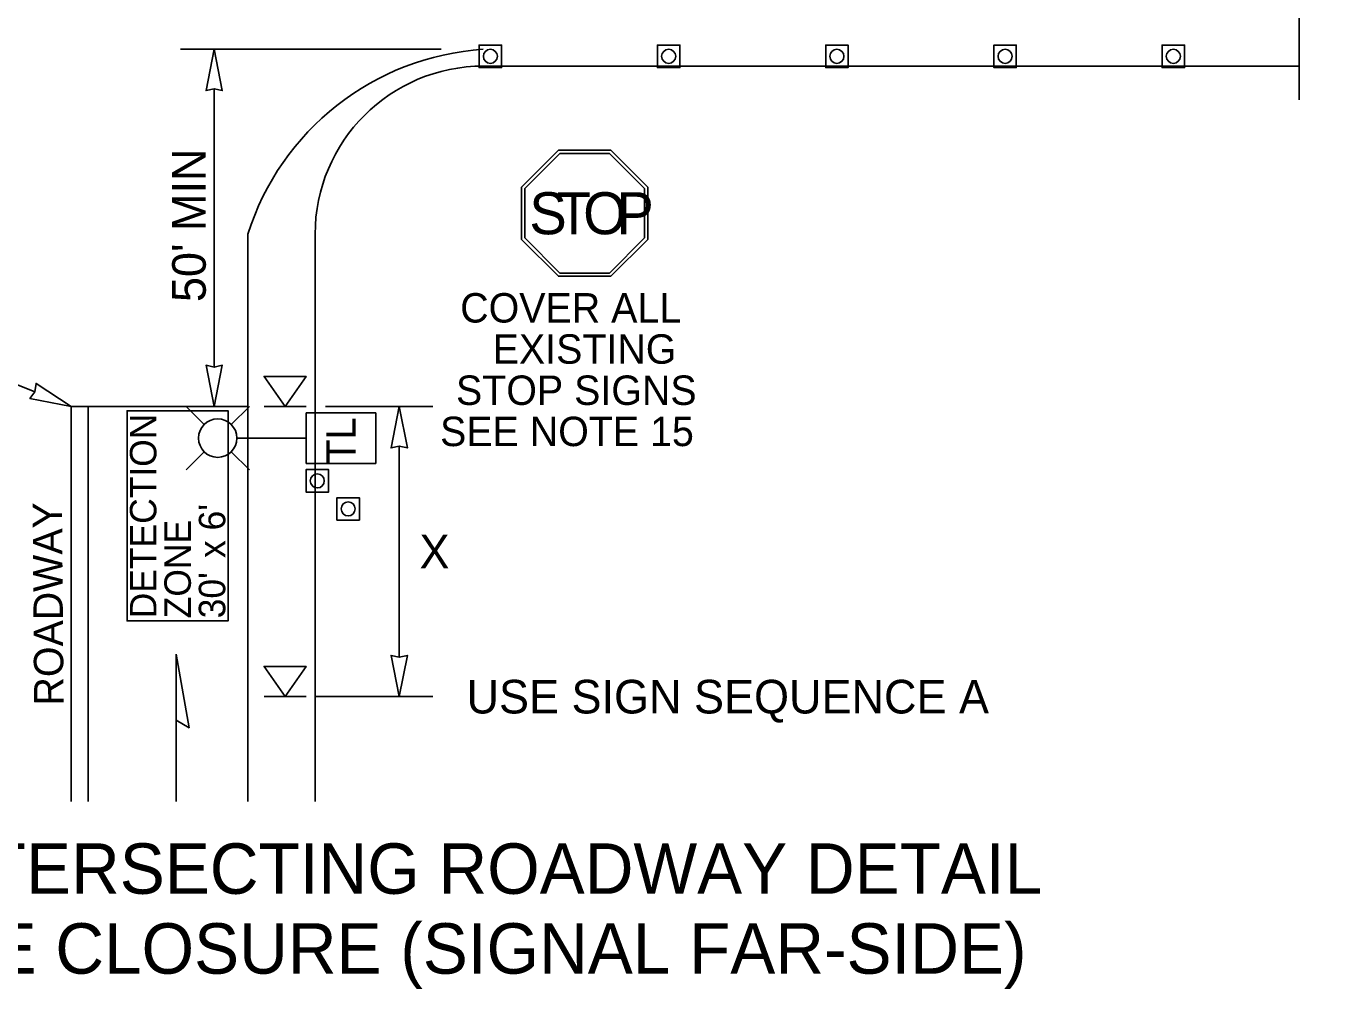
# Model space of a CAD drawing. Extents: x 99979.8 to 100075.7, y 99995 to 100010.7.
# Drawn here: x 100041.998 to 100045.105, y 100006.224 to 100008.515 of the extents above; entities that cross this region are included whole.
import ezdxf

# ---------------------------------------------------------------- set-up
doc = ezdxf.new("R2010")
doc.units = 0
for name, color, linetype in [('RD_ED_ShoulderPavedEdge', 7, 'Continuous'), ('RD_MK_LineDblYellowCenter', 7, 'Continuous'), ('RD_MK_LineEdgeWhite', 7, 'Continuous'), ('RD_MK_LineStop', 7, 'Continuous'), ('SH_DE_DetailBody1Text', 7, 'Continuous'), ('SH_DE_DetailHeading2Text', 7, 'Continuous'), ('TR_SN_ConstructionSigns', 7, 'Continuous'), ('TR_WZ_PortableLightStandard', 7, 'Continuous'), ('TR_WZ_PortableSignMountBlk-Org', 7, 'Continuous'), ('TR_WZ_PortableSignMountBlk-Wht', 7, 'Continuous'), ('TR_WZ_TrafficCone', 7, 'Continuous'), ('TR_WZ_WorkZoneDetails', 7, 'Continuous'), ('TR_WZ_WorkZoneTextCurrent', 7, 'Continuous')]:
    doc.layers.add(name, color=color, linetype=linetype)

msp = doc.modelspace()

# ---------------------------------------------------------------- linework, layer by layer
at = {"layer": 'RD_ED_ShoulderPavedEdge'}
msp.add_line((100043.085, 100008.4195), (100045.025, 100008.4195), dxfattribs=at)
msp.add_lwpolyline([(100042.685, 100006.6704), (100042.685, 100008.0195)], dxfattribs=at)
msp.add_arc((100043.085, 100008.0195), 0.4, 90, 180, dxfattribs=at)
at = {"layer": 'RD_MK_LineDblYellowCenter'}
for p, q in [((100042.105, 100006.6704), (100042.105, 100007.6095)), ((100042.145, 100006.6704), (100042.145, 100007.6095))]:
    msp.add_line(p, q, dxfattribs=at)
at = {"layer": 'RD_MK_LineEdgeWhite'}
msp.add_line((100042.525, 100008.0195), (100042.525, 100006.6704), dxfattribs=at)
msp.add_arc((100043.1265, 100007.8303), 0.6306, 93.7766, 162.5378, dxfattribs=at)
at = {"layer": 'RD_MK_LineStop'}
msp.add_line((100042.525, 100007.6095), (100042.105, 100007.6095), dxfattribs=at)
at = {"layer": 'TR_SN_ConstructionSigns'}
for p, q in [((100043.2637, 100008.2195), (100043.1758, 100008.1316)), ((100043.2637, 100008.2195), (100043.1758, 100008.1316)), ((100043.1836, 100008.1284), (100043.2669, 100008.2117)), ((100043.3879, 100008.2195), (100043.2637, 100008.2195)), ((100043.3879, 100008.2195), (100043.2637, 100008.2195)), ((100043.2669, 100008.2117), (100043.3847, 100008.2117)), ((100043.3847, 100008.2117), (100043.468, 100008.1284)), ((100043.4758, 100008.1316), (100043.3879, 100008.2195)), ((100043.4758, 100008.1316), (100043.3879, 100008.2195)), ((100043.1758, 100008.1316), (100043.1758, 100008.0073)), ((100043.1758, 100008.1316), (100043.1758, 100008.0073)), ((100043.1836, 100008.0106), (100043.1836, 100008.1284)), ((100043.468, 100008.1284), (100043.468, 100008.0106)), ((100043.4758, 100008.0073), (100043.4758, 100008.1316)), ((100043.4758, 100008.0073), (100043.4758, 100008.1316)), ((100043.1758, 100008.0073), (100043.2637, 100007.9195)), ((100043.1758, 100008.0073), (100043.2637, 100007.9195)), ((100043.2669, 100007.9273), (100043.1836, 100008.0106)), ((100043.468, 100008.0106), (100043.3847, 100007.9273)), ((100043.3879, 100007.9195), (100043.4758, 100008.0073)), ((100043.3879, 100007.9195), (100043.4758, 100008.0073)), ((100043.3847, 100007.9273), (100043.2669, 100007.9273)), ((100043.2637, 100007.9195), (100043.3879, 100007.9195)), ((100043.2637, 100007.9195), (100043.3879, 100007.9195))]:
    msp.add_line(p, q, dxfattribs=at)
msp.add_lwpolyline([(100043.2637, 100008.2195), (100043.3879, 100008.2195), (100043.4758, 100008.1316), (100043.4758, 100008.0073), (100043.3879, 100007.9195), (100043.2637, 100007.9195), (100043.1758, 100008.0073), (100043.1758, 100008.1316), (100043.2637, 100008.2195)], dxfattribs=at)
at = {"layer": 'TR_WZ_PortableLightStandard'}
for p, q in [((100042.4211, 100007.5669), (100042.378, 100007.6098)), ((100042.4857, 100007.5669), (100042.5288, 100007.6098)), ((100042.8295, 100007.5945), (100042.6636, 100007.5945)), ((100042.6636, 100007.5945), (100042.6636, 100007.4745)), ((100042.8295, 100007.5945), (100042.6636, 100007.5945)), ((100042.8295, 100007.5945), (100042.8295, 100007.4745)), ((100042.6636, 100007.5345), (100042.4992, 100007.5345)), ((100042.4211, 100007.5021), (100042.378, 100007.459)), ((100042.4857, 100007.5021), (100042.5288, 100007.459)), ((100042.8295, 100007.4745), (100042.6636, 100007.4745)), ((100042.6636, 100007.4745), (100042.8295, 100007.4745))]:
    msp.add_line(p, q, dxfattribs=at)
for points in [[(100042.6636, 100007.5945), (100042.6636, 100007.5345), (100042.6636, 100007.4745)], [(100042.8295, 100007.4745), (100042.8295, 100007.5345), (100042.8295, 100007.5945)]]:
    msp.add_lwpolyline(points, dxfattribs=at)
msp.add_circle((100042.4534, 100007.5345), 0.0457, dxfattribs=at)
msp.add_circle((100042.4534, 100007.5345), 0.0457, dxfattribs=at)
at = {"layer": 'TR_WZ_PortableSignMountBlk-Org'}
msp.add_line((100042.6636, 100006.9195), (100042.5636, 100006.9195), dxfattribs=at)
msp.add_lwpolyline([(100042.6137, 100006.9195), (100042.5636, 100006.9913), (100042.6636, 100006.9913)], close=True, dxfattribs=at)
at = {"layer": 'TR_WZ_PortableSignMountBlk-Wht'}
msp.add_line((100042.6636, 100007.6095), (100042.5636, 100007.6095), dxfattribs=at)
msp.add_lwpolyline([(100042.6137, 100007.6095), (100042.5636, 100007.6813), (100042.6636, 100007.6813)], close=True, dxfattribs=at)
at = {"layer": 'TR_WZ_TrafficCone'}
for points in [[(100043.075, 100008.4695), (100043.1283, 100008.4695), (100043.1283, 100008.4161), (100043.075, 100008.4161), (100043.075, 100008.4695)], [(100043.075, 100008.4161), (100043.1283, 100008.4161), (100043.1283, 100008.4695), (100043.075, 100008.4695), (100043.075, 100008.4161)], [(100043.499, 100008.4695), (100043.5523, 100008.4695), (100043.5523, 100008.4161), (100043.499, 100008.4161), (100043.499, 100008.4695)], [(100043.499, 100008.4161), (100043.5523, 100008.4161), (100043.5523, 100008.4695), (100043.499, 100008.4695), (100043.499, 100008.4161)], [(100043.899, 100008.4695), (100043.9523, 100008.4695), (100043.9523, 100008.4161), (100043.899, 100008.4161), (100043.899, 100008.4695)], [(100043.899, 100008.4161), (100043.9523, 100008.4161), (100043.9523, 100008.4695), (100043.899, 100008.4695), (100043.899, 100008.4161)], [(100044.299, 100008.4695), (100044.3523, 100008.4695), (100044.3523, 100008.4161), (100044.299, 100008.4161), (100044.299, 100008.4695)], [(100044.299, 100008.4161), (100044.3523, 100008.4161), (100044.3523, 100008.4695), (100044.299, 100008.4695), (100044.299, 100008.4161)], [(100044.699, 100008.4695), (100044.7523, 100008.4695), (100044.7523, 100008.4161), (100044.699, 100008.4161), (100044.699, 100008.4695)], [(100044.699, 100008.4161), (100044.7523, 100008.4161), (100044.7523, 100008.4695), (100044.699, 100008.4695), (100044.699, 100008.4161)], [(100042.6636, 100007.4061), (100042.6636, 100007.4595), (100042.7169, 100007.4595), (100042.7169, 100007.4061), (100042.6636, 100007.4061)], [(100042.7169, 100007.4061), (100042.7169, 100007.4595), (100042.6636, 100007.4595), (100042.6636, 100007.4061), (100042.7169, 100007.4061)], [(100042.7369, 100007.3395), (100042.7369, 100007.3928), (100042.7902, 100007.3928), (100042.7902, 100007.3395), (100042.7369, 100007.3395)], [(100042.7902, 100007.3395), (100042.7902, 100007.3928), (100042.7369, 100007.3928), (100042.7369, 100007.3395), (100042.7902, 100007.3395)]]:
    msp.add_lwpolyline(points, dxfattribs=at)
for centre in [(100043.1017, 100008.4428), (100043.5257, 100008.4428), (100043.9257, 100008.4428), (100044.3257, 100008.4428), (100044.7257, 100008.4428), (100042.6902, 100007.4328), (100042.7636, 100007.3661)]:
    msp.add_circle(centre, 0.0167, dxfattribs=at)
at = {"layer": 'TR_WZ_WorkZoneDetails'}
for p, q in [((100042.365, 100008.4595), (100042.985, 100008.4595)), ((100042.445, 100008.3657), (100042.445, 100007.7032)), ((100043.1758, 100008.1316), (100043.2637, 100008.2195)), ((100043.2637, 100008.2195), (100043.1758, 100008.1316)), ((100043.2637, 100008.2195), (100043.2637, 100008.2195)), ((100043.2637, 100008.2195), (100043.3879, 100008.2195)), ((100043.3879, 100008.2195), (100043.2637, 100008.2195)), ((100043.3879, 100008.2195), (100043.4758, 100008.1316)), ((100043.4758, 100008.1316), (100043.3879, 100008.2195)), ((100043.1758, 100008.1316), (100043.1758, 100008.1316)), ((100043.1758, 100008.0073), (100043.1758, 100008.1316)), ((100043.1758, 100008.1316), (100043.1758, 100008.0073)), ((100043.4758, 100008.1316), (100043.4758, 100008.1316)), ((100043.4758, 100008.1316), (100043.4758, 100008.0073)), ((100043.4758, 100008.0073), (100043.4758, 100008.1316)), ((100043.1758, 100008.0073), (100043.1758, 100008.0073)), ((100043.2637, 100007.9195), (100043.1758, 100008.0073)), ((100043.1758, 100008.0073), (100043.2637, 100007.9195)), ((100043.4758, 100008.0073), (100043.3879, 100007.9195)), ((100043.3879, 100007.9195), (100043.4758, 100008.0073)), ((100043.4758, 100008.0073), (100043.4758, 100008.0073)), ((100043.2637, 100007.9195), (100043.2637, 100007.9195)), ((100043.3879, 100007.9195), (100043.2637, 100007.9195)), ((100043.2637, 100007.9195), (100043.3879, 100007.9195)), ((100043.3879, 100007.9195), (100043.3879, 100007.9195)), ((100041.6052, 100007.8103), (100042.0183, 100007.645)), ((100042.7095, 100007.6095), (100042.965, 100007.6095)), ((100042.885, 100007.5157), (100042.885, 100007.0132)), ((100042.685, 100006.9195), (100042.965, 100006.9195)), ((100042.3545, 100006.8633), (100042.3545, 100006.6704))]:
    msp.add_line(p, q, dxfattribs=at)
for points in [[(100045.025, 100008.3395), (100045.025, 100009.2221), (100044.945, 100009.2221), (100045.105, 100009.3769), (100045.025, 100009.3769), (100045.025, 100010.2595)], [(100045.025, 100008.3395), (100045.025, 100009.2221), (100044.945, 100009.2221), (100045.105, 100009.3769), (100045.025, 100009.3769), (100045.025, 100010.2595)], [(100042.478, 100007.0995), (100042.478, 100007.5995), (100042.238, 100007.5995), (100042.238, 100007.0995), (100042.478, 100007.0995)], [(100042.238, 100007.0995), (100042.238, 100007.5995), (100042.478, 100007.5995), (100042.478, 100007.0995), (100042.238, 100007.0995)]]:
    msp.add_lwpolyline(points, dxfattribs=at)
for points in [[(100042.445, 100008.4595), (100042.4257, 100008.3612), (100042.445, 100008.3657), (100042.4643, 100008.3612)], [(100042.445, 100007.6095), (100042.4257, 100007.7078), (100042.445, 100007.7032), (100042.4643, 100007.7078)], [(100042.105, 100007.6095), (100042.0068, 100007.6289), (100042.0183, 100007.645), (100042.0214, 100007.6646)], [(100042.885, 100007.6095), (100042.8657, 100007.5112), (100042.885, 100007.5157), (100042.9043, 100007.5112)], [(100042.3545, 100007.0206), (100042.3854, 100006.8455), (100042.3545, 100006.8633)], [(100042.885, 100006.9195), (100042.8657, 100007.0178), (100042.885, 100007.0132), (100042.9043, 100007.0178)]]:
    msp.add_lwpolyline(points, close=True, dxfattribs=at)

# ---------------------------------------------------------------- texts
at = {"layer": 'SH_DE_DetailBody1Text'}
msp.add_text('ROADWAY', height=0.07, rotation=90.4626, dxfattribs=at).set_placement((100042.087, 100006.8987))
at = {"layer": 'SH_DE_DetailHeading2Text'}
for s, p in [('UNSIGNALIZED INTERSECTING ROADWAY DETAIL', (100040.5086, 100006.4505)), ('OPPOSITE OF LANE CLOSURE (SIGNAL FAR-SIDE)', (100040.4711, 100006.2605))]:
    msp.add_text(s, height=0.12, rotation=360, dxfattribs=at).set_placement(p)
at = {"layer": 'TR_SN_ConstructionSigns'}
for s, p in [('COVER ALL', (100043.03, 100007.8095)), ('EXISTING', (100043.1072, 100007.7115)), ('STOP SIGNS', (100043.02, 100007.6135)), ('SEE NOTE 15', (100042.9821, 100007.5155))]:
    msp.add_text(s, height=0.07, dxfattribs=at).set_placement(p)
at = {"layer": 'TR_WZ_PortableLightStandard'}
msp.add_text('TL', height=0.07, rotation=90, dxfattribs=at).set_placement((100042.7816, 100007.4743))
at = {"layer": 'TR_WZ_WorkZoneDetails'}
for s, p in [('S', (100043.1943, 100008.0195)), ('T', (100043.2593, 100008.0195)), ('O', (100043.3223, 100008.0195)), ('P', (100043.4013, 100008.0195))]:
    msp.add_text(s, height=0.1, dxfattribs=at).set_placement(p)
for s, p in [('DETECTION', (100042.3076, 100007.1059)), ("x 6'", (100042.4714, 100007.2494)), ('ZONE', (100042.3895, 100007.1059)), ("30'", (100042.4714, 100007.1059))]:
    msp.add_text(s, height=0.063, rotation=90, dxfattribs=at).set_placement(p)
at = {"layer": 'TR_WZ_WorkZoneTextCurrent'}
msp.add_text("50' MIN", height=0.08, rotation=90, dxfattribs=at).set_placement((100042.425, 100007.8582))
for s, p in [('X', (100042.9332, 100007.2245)), ('USE SIGN SEQUENCE A', (100043.045, 100006.8795))]:
    msp.add_text(s, height=0.08, dxfattribs=at).set_placement(p)

doc.saveas('drawing.dxf')
